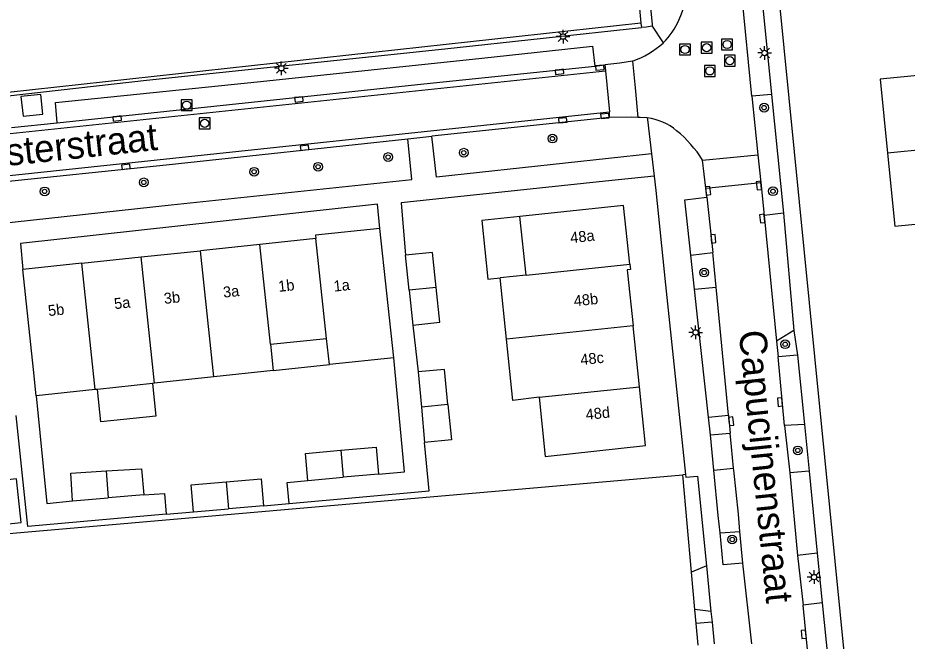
# Model space of a CAD drawing. Extents: x 140000 to 143000, y 403500 to 406000.
# Drawn here: x 140498.4 to 140579.8, y 403927.8 to 403984.8 of the extents above; entities that cross this region are included whole.
import ezdxf

# ---------------------------------------------------------------- set-up
doc = ezdxf.new("R2010")
doc.units = 0
for name, color, linetype in [('gg-afsc-erfafscheiding', 7, 'Continuous'), ('gg-afsc-hekwerk', 7, 'Continuous'), ('gg-anno-huisnummerreeks BGT', 7, 'Continuous'), ('gg-anno-openbare ruimte label', 7, 'Continuous'), ('gg-bbg-bijgebouw', 7, 'Continuous'), ('gg-bbg-hoofdgebouw', 7, 'Continuous'), ('gg-bbg-luifel en loopbrug', 7, 'Continuous'), ('gg-bbg-tussenscheiding', 7, 'Continuous'), ('gg-knt-verharding', 7, 'Continuous'), ('gg-knt-verharding nz', 7, 'Continuous'), ('gg-kwrk-afval apart plaats', 7, 'Continuous'), ('gt-grn-groengrens', 7, 'Continuous'), ('gt-grn-weggrens', 7, 'Continuous'), ('gt-symb-boom', 7, 'Continuous'), ('gt-symb-kolk', 7, 'Continuous'), ('gt-symb-lichtmast', 7, 'Continuous'), ('gt-symb-rioolschacht', 7, 'Continuous')]:
    doc.layers.add(name, color=color, linetype=linetype)

# ---------------------------------------------------------------- blocks, each defined once
blk = doc.blocks.new('gt0-BOOM')
at = {"layer": 'gt-symb-boom'}
for radius in [0.4, 0.2]:
    blk.add_circle((0, 0), radius, dxfattribs=at)
blk = doc.blocks.new('gt0-RS')
at = {"layer": 'gt-symb-rioolschacht'}
blk.add_lwpolyline([(-0.5, -0.5), (0.5, -0.5), (0.5, 0.5), (-0.5, 0.5)], close=True, dxfattribs=at)
blk.add_circle((0, 0), 0.375, dxfattribs=at)
blk = doc.blocks.new('gt0-KOLK')
at = {"layer": 'gt-symb-kolk'}
blk.add_lwpolyline([(0, 0), (0.375, 0), (0.375, 0.4), (-0.375, 0.4), (-0.375, 0), (0, 0)], dxfattribs=at)
blk = doc.blocks.new('gt0-LMAST')
at = {"layer": 'gt-symb-lichtmast'}
for p, q in [((-0.182, 0.173), (-0.447, 0.438)), ((-0.005, 0.246), (-0.005, 0.621)), ((0.172, 0.173), (0.437, 0.438)), ((-0.255, -0.004), (-0.63, -0.004)), ((-0.182, -0.181), (-0.447, -0.446)), ((-0.005, -0.254), (-0.005, -0.629)), ((0.437, -0.446), (0.172, -0.181)), ((0.245, -0.004), (0.62, -0.004))]:
    blk.add_line(p, q, dxfattribs=at)
blk.add_circle((-0.005, -0.004), 0.25, dxfattribs=at)

msp = doc.modelspace()

# ---------------------------------------------------------------- linework, layer by layer
at = {"layer": 'gg-afsc-erfafscheiding'}
for p, q in [((140477.872, 403935.89), (140559.274, 403942.987)), ((140559.502, 403943.006), (140559.274, 403942.987)), ((140560.063, 403934.086), (140559.274, 403942.987)), ((140520.86, 403940.149), (140523.207, 403940.362)), ((140511.943, 403939.396), (140514.462, 403939.588)), ((140560.481, 403929.367), (140560.368, 403930.645)), ((140560.657, 403927.39), (140560.481, 403929.367))]:
    msp.add_line(p, q, dxfattribs=at)
at = {"layer": 'gg-afsc-hekwerk'}
msp.add_lwpolyline([(140555.427, 403984.336), (140484.069, 403976.529), (140484.106, 403976.189)], dxfattribs=at)
at = {"layer": 'gg-bbg-bijgebouw'}
for p, q in [((140534.208, 403959.896), (140533.866, 403963.1)), ((140534.208, 403959.896), (140534.549, 403956.691)), ((140535.013, 403952.41), (140535.314, 403949.178)), ((140535.314, 403949.178), (140535.614, 403945.946)), ((140524.935, 403942.467), (140528.169, 403942.76)), ((140531.402, 403943.053), (140528.169, 403942.76)), ((140503.364, 403940.596), (140506.632, 403940.877)), ((140509.9, 403941.157), (140506.632, 403940.877)), ((140520.86, 403940.149), (140517.661, 403939.868)), ((140514.462, 403939.588), (140517.661, 403939.868))]:
    msp.add_line(p, q, dxfattribs=at)
for points in [[(140536.673, 403960.153), (140536.347, 403963.353), (140533.866, 403963.1)], [(140534.549, 403956.691), (140536.999, 403956.952), (140536.673, 403960.153)], [(140537.75, 403949.416), (140537.42, 403952.634), (140535.013, 403952.41)], [(140537.75, 403949.416), (140538.079, 403946.199), (140535.614, 403945.946)], [(140524.935, 403942.467), (140524.71, 403944.953), (140527.947, 403945.239)], [(140527.947, 403945.239), (140531.184, 403945.525), (140531.402, 403943.053)], [(140503.364, 403940.596), (140503.21, 403943.155), (140506.453, 403943.349)], [(140506.453, 403943.349), (140509.695, 403943.543), (140509.9, 403941.157)], [(140514.462, 403939.588), (140514.244, 403942.073), (140517.445, 403942.349)], [(140517.445, 403942.349), (140520.646, 403942.626), (140520.86, 403940.149)]]:
    msp.add_lwpolyline(points, dxfattribs=at)
at = {"layer": 'gg-bbg-hoofdgebouw'}
for p, q in [((140544.903, 403961.261), (140544.335, 403966.631)), ((140532.788, 403953.69), (140531.511, 403965.534)), ((140525.666, 403964.619), (140520.534, 403964.078)), ((140509.668, 403962.933), (140515.095, 403963.505)), ((140520.534, 403964.078), (140515.095, 403963.505)), ((140504.24, 403962.362), (140509.668, 403962.933)), ((140504.24, 403962.362), (140498.839, 403961.793)), ((140544.903, 403961.261), (140542.522, 403961.009)), ((140543.106, 403955.405), (140542.522, 403961.009)), ((140555.285, 403951.051), (140554.705, 403956.615)), ((140521.496, 403954.942), (140526.629, 403955.48)), ((140526.911, 403953.097), (140526.629, 403955.48)), ((140521.496, 403954.942), (140521.739, 403952.537)), ((140532.788, 403953.69), (140526.911, 403953.097)), ((140521.739, 403952.537), (140516.312, 403951.954)), ((140510.686, 403951.351), (140505.658, 403950.81)), ((140510.885, 403951.372), (140510.686, 403951.351)), ((140516.312, 403951.954), (140510.885, 403951.372)), ((140505.459, 403950.789), (140500.032, 403950.206)), ((140505.658, 403950.81), (140505.459, 403950.789))]:
    msp.add_line(p, q, dxfattribs=at)
for points in [[(140589.429, 403973.63), (140589.2, 403975.972), (140588.769, 403980.314), (140583.89, 403979.841), (140577.33, 403979.202), (140578.011, 403972.421)], [(140578.011, 403972.421), (140578.68, 403965.752), (140583.65, 403966.252), (140585.427, 403966.431), (140590.354, 403966.909), (140589.976, 403970.299), (140593.202, 403970.617), (140592.922, 403973.971), (140589.429, 403973.63)], [(140554.404, 403962.289), (140553.825, 403967.639), (140544.335, 403966.631)], [(140531.511, 403965.534), (140531.506, 403965.526), (140525.635, 403964.916), (140525.666, 403964.619)], [(140554.404, 403962.289), (140554.458, 403961.798), (140554.168, 403961.768), (140554.202, 403961.442), (140554.705, 403956.615)], [(140500.032, 403950.206), (140499.796, 403952.62), (140498.839, 403961.793)], [(140546.117, 403950.095), (140543.689, 403949.802), (140543.106, 403955.405)], [(140546.117, 403950.095), (140546.658, 403944.678), (140555.847, 403945.663), (140555.285, 403951.051)]]:
    msp.add_lwpolyline(points, dxfattribs=at)
at = {"layer": 'gg-bbg-luifel en loopbrug'}
msp.add_line((140521.739, 403952.537), (140526.911, 403953.097), dxfattribs=at)
for points in [[(140544.335, 403966.631), (140540.852, 403966.262), (140541.415, 403960.898), (140542.522, 403961.009)], [(140510.686, 403951.351), (140511.007, 403948.368), (140505.978, 403947.828), (140505.658, 403950.81)], [(140495.274, 403942.301), (140495.682, 403938.322), (140498.666, 403938.628), (140498.258, 403942.607), (140495.274, 403942.301)]]:
    msp.add_lwpolyline(points, dxfattribs=at)
at = {"layer": 'gg-bbg-tussenscheiding'}
for p, q in [((140589.429, 403973.63), (140578.011, 403972.421)), ((140526.629, 403955.48), (140525.666, 403964.619)), ((140516.312, 403951.954), (140515.095, 403963.505)), ((140521.496, 403954.942), (140520.534, 403964.078)), ((140510.885, 403951.372), (140509.668, 403962.933)), ((140505.459, 403950.789), (140504.24, 403962.362)), ((140544.903, 403961.261), (140554.404, 403962.289)), ((140536.673, 403960.153), (140534.208, 403959.896)), ((140554.705, 403956.615), (140543.106, 403955.405)), ((140546.117, 403950.095), (140555.285, 403951.051)), ((140537.75, 403949.416), (140535.314, 403949.178)), ((140527.947, 403945.239), (140528.169, 403942.76)), ((140506.453, 403943.349), (140506.632, 403940.877)), ((140517.445, 403942.349), (140517.661, 403939.868))]:
    msp.add_line(p, q, dxfattribs=at)
at = {"layer": 'gg-knt-verharding'}
for p, q in [((140604.366, 403622.979), (140559.755, 404069.979)), ((140566.385, 403987.711), (140567.367, 403977.797)), ((140556.458, 403984.071), (140557.473, 403982.548)), ((140551.189, 403980.409), (140552.107, 403980.509)), ((140552.107, 403980.509), (140552.175, 403979.979)), ((140552.175, 403979.979), (140552.551, 403976.217)), ((140567.367, 403977.797), (140565.589, 403977.649)), ((140565.589, 403977.649), (140566.133, 403972.297)), ((140567.367, 403977.797), (140568.47, 403966.951)), ((140552.557, 403975.687), (140552.551, 403976.217)), ((140497.791, 403974.795), (140501.969, 403975.223)), ((140552.557, 403975.687), (140536.289, 403973.981)), ((140534.063, 403973.743), (140536.289, 403973.981)), ((140556.404, 403972.362), (140556.626, 403970.345)), ((140561.072, 403971.806), (140566.133, 403972.297)), ((140561.352, 403969.231), (140561.072, 403971.806)), ((140566.133, 403972.297), (140566.392, 403969.753)), ((140561.352, 403969.231), (140566.392, 403969.753)), ((140561.442, 403968.396), (140561.352, 403969.231)), ((140566.392, 403969.753), (140566.7, 403966.719)), ((140568.47, 403966.951), (140566.7, 403966.719)), ((140568.47, 403966.951), (140569.432, 403956.215)), ((140559.999, 403963.109), (140561.992, 403963.33)), ((140560.33, 403959.981), (140559.999, 403963.109)), ((140562.298, 403960.171), (140561.992, 403963.33)), ((140560.33, 403959.981), (140562.298, 403960.171)), ((140534.549, 403956.691), (140535.013, 403952.41)), ((140569.432, 403956.215), (140567.837, 403955.236)), ((140569.432, 403956.215), (140569.755, 403953.93)), ((140567.837, 403955.236), (140568, 403953.786)), ((140569.755, 403953.93), (140568, 403953.786)), ((140569.755, 403953.93), (140570.404, 403947.6)), ((140561.61, 403948.258), (140563.43, 403948.446)), ((140561.782, 403946.641), (140561.61, 403948.258)), ((140563.43, 403948.446), (140563.588, 403946.815)), ((140570.404, 403947.6), (140568.561, 403947.493)), ((140568.561, 403947.493), (140569.048, 403943.159)), ((140570.404, 403947.6), (140570.82, 403943.334)), ((140561.782, 403946.641), (140563.588, 403946.815)), ((140562.099, 403943.418), (140561.782, 403946.641)), ((140562.099, 403943.418), (140563.913, 403943.592)), ((140570.82, 403943.334), (140569.048, 403943.159)), ((140570.82, 403943.334), (140571.547, 403935.81)), ((140562.663, 403937.675), (140564.488, 403937.808)), ((140564.744, 403934.909), (140564.488, 403937.808)), ((140571.547, 403935.81), (140569.766, 403935.612)), ((140569.766, 403935.612), (140570.278, 403931.048)), ((140571.547, 403935.81), (140572.017, 403931.277)), ((140561.417, 403934.665), (140560.063, 403934.086)), ((140561.417, 403934.665), (140561.836, 403930.465)), ((140565.565, 403927.508), (140564.744, 403934.909)), ((140560.368, 403930.645), (140560.063, 403934.086)), ((140572.017, 403931.277), (140570.278, 403931.048)), ((140572.017, 403931.277), (140572.655, 403924.957)), ((140561.836, 403930.465), (140560.368, 403930.645)), ((140561.836, 403930.465), (140561.933, 403929.496)), ((140561.933, 403929.496), (140560.481, 403929.367)), ((140561.933, 403929.496), (140562.13, 403927.521))]:
    msp.add_line(p, q, dxfattribs=at)
for points in [[(140546.163, 404087.643), (140556.445, 403984.205), (140556.458, 403984.071)], [(140484.494, 403976.231), (140510.138, 403979.108), (140537.462, 403981.986), (140555.467, 403983.938)], [(140556.458, 403984.071), (140555.896, 403983.984), (140555.467, 403983.938)], [(140501.969, 403975.223), (140501.817, 403977.063), (140520.589, 403978.991), (140540.863, 403981.13), (140551.001, 403982.234), (140551.189, 403980.409)], [(140554.638, 403980.847), (140553.476, 403980.668), (140552.107, 403980.509)], [(140554.638, 403980.847), (140554.895, 403978.412), (140555.126, 403975.712)], [(140501.969, 403975.223), (140535.542, 403978.791), (140551.189, 403980.409)], [(140555.126, 403975.712), (140554.592, 403975.732), (140552.557, 403975.687)], [(140556.007, 403975.668), (140555.364, 403975.703), (140555.126, 403975.712)], [(140556.007, 403975.668), (140556.026, 403975.508), (140556.404, 403972.362)], [(140496.008, 403969.714), (140496.405, 403965.97), (140512.411, 403967.715), (140534.443, 403970.018), (140534.063, 403973.743)], [(140496.008, 403969.714), (140511.958, 403971.373), (140534.063, 403973.743)], [(140556.404, 403972.362), (140536.696, 403970.244), (140536.289, 403973.981)], [(140556.626, 403970.345), (140552.189, 403969.88), (140533.453, 403967.901), (140533.866, 403963.1)], [(140556.626, 403970.345), (140556.774, 403969.02), (140557.667, 403960.371), (140559.502, 403943.006)], [(140559.999, 403963.109), (140559.451, 403968.159), (140561.442, 403968.396)], [(140531.511, 403965.534), (140531.296, 403967.764), (140498.601, 403964.167), (140498.839, 403961.793)], [(140561.61, 403948.258), (140560.641, 403957.136), (140560.33, 403959.981)], [(140563.43, 403948.446), (140562.573, 403957.322), (140562.298, 403960.171)], [(140531.402, 403943.053), (140533.759, 403943.267), (140532.788, 403953.69)], [(140500.032, 403950.206), (140501.03, 403940.359), (140503.364, 403940.596)], [(140511.943, 403939.396), (140499.268, 403938.257), (140498.226, 403948.429)], [(140523.207, 403940.362), (140536.045, 403941.529), (140535.614, 403945.946)], [(140562.663, 403937.675), (140562.507, 403939.259), (140562.099, 403943.418)], [(140564.488, 403937.808), (140564.348, 403939.393), (140563.932, 403943.407), (140563.913, 403943.592)], [(140523.207, 403940.362), (140523.032, 403942.294), (140524.935, 403942.467)], [(140559.502, 403943.006), (140559.527, 403942.774), (140560.598, 403942.863), (140561.417, 403934.665)], [(140509.9, 403941.157), (140511.782, 403941.28), (140511.943, 403939.396)], [(140564.744, 403934.909), (140562.951, 403934.736), (140562.663, 403937.675)]]:
    msp.add_lwpolyline(points, dxfattribs=at)
for centre, radius, start, end in [((140553.471, 403987.249), 6.036, 334.25297, 7.6851), ((140552.839, 403987.278), 6.622, 314.41011, 336.39759), ((140551.833, 403988.736), 8.373, 289.57671, 312.35081), ((140555.345, 403970.506), 5.205, 49.98882, 82.68973), ((140551.54, 403965.754), 11.291, 32.40934, 50.70132)]:
    msp.add_arc(centre, radius, start, end, dxfattribs=at)
at = {"layer": 'gg-knt-verharding nz'}
for p, q in [((140565.589, 403977.649), (140564.596, 403987.532)), ((140561.442, 403968.396), (140561.992, 403963.33)), ((140566.7, 403966.719), (140567.837, 403955.236)), ((140568.561, 403947.493), (140568, 403953.786)), ((140569.048, 403943.159), (140569.766, 403935.612))]:
    msp.add_line(p, q, dxfattribs=at)
for points in [[(140563.913, 403943.592), (140563.71, 403945.542), (140563.588, 403946.815)], [(140570.877, 403924.813), (140570.874, 403924.838), (140570.278, 403931.048)]]:
    msp.add_lwpolyline(points, dxfattribs=at)
at = {"layer": 'gg-kwrk-afval apart plaats'}
msp.add_lwpolyline([(140498.655, 403977.622), (140498.847, 403975.815), (140500.651, 403976.003), (140500.466, 403977.82), (140498.655, 403977.622)], dxfattribs=at)
at = {"layer": 'gt-grn-groengrens'}
for p, q in [((140545.173, 404087.488), (140555.427, 403984.336)), ((140555.427, 403984.336), (140555.467, 403983.938))]:
    msp.add_line(p, q, dxfattribs=at)
at = {"layer": 'gt-grn-weggrens'}
msp.add_line((140480.72, 403972.447), (140552.175, 403979.979), dxfattribs=at)
msp.add_lwpolyline([(140481.112, 403968.667), (140490.084, 403969.605), (140552.551, 403976.217)], dxfattribs=at)

# ---------------------------------------------------------------- block references
at = {"layer": 'gt-symb-boom'}
for p in [(140566.7, 403976.601), (140547.318, 403973.767), (140532.266, 403972.082), (140539.197, 403972.479), (140520.004, 403970.737), (140525.862, 403971.195), (140509.902, 403969.763), (140500.821, 403968.937), (140567.514, 403968.946), (140561.212, 403961.503), (140568.628, 403954.943), (140569.787, 403945.224), (140563.781, 403937.067)]:
    msp.add_blockref('gt0-BOOM', p, dxfattribs=at)
at = {"layer": 'gt-symb-kolk'}
for p, rotation in [((140547.946, 403980.074), -174.0982878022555), ((140551.637, 403980.458), -174.01718369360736), ((140524.084, 403977.553), -174.52065066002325), ((140507.441, 403975.805), -173.93608067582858), ((140552.143, 403975.644), 5.990842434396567), ((140548.287, 403975.239), 5.990842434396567), ((140524.638, 403972.732), 6.120088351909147), ((140508.288, 403970.991), 5.941846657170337), ((140561.38, 403968.975), -83.83090908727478), ((140566.418, 403969.492), 95.80373342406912), ((140566.724, 403966.472), 95.65839657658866), ((140561.857, 403964.574), -83.80684128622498), ((140568.367, 403949.665), 95.09068261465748), ((140563.485, 403947.878), -84.46365037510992), ((140570.532, 403928.404), 95.47934933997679)]:
    msp.add_blockref('gt0-KOLK', p, dxfattribs=dict(at, rotation=rotation))
at = {"layer": 'gt-symb-lichtmast'}
for p in [(140548.292, 403983.112), (140566.744, 403981.612), (140522.497, 403980.22), (140560.43, 403956.025), (140571.283, 403933.628)]:
    msp.add_blockref('gt0-LMAST', p, dxfattribs=at)
at = {"layer": 'gt-symb-rioolschacht'}
for p in [(140559.457, 403981.927), (140561.436, 403982.093), (140563.313, 403982.385), (140563.564, 403980.898), (140561.729, 403979.968), (140513.821, 403976.827), (140515.476, 403975.166)]:
    msp.add_blockref('gt0-RS', p, dxfattribs=at)

# ---------------------------------------------------------------- texts
at = {"layer": 'gg-anno-huisnummerreeks BGT'}
for s, rotation, p in [('48a', 6.2, (140549.002, 403964.194)), ('3a', 6, (140517.209, 403959.204)), ('1b', 6, (140522.259, 403959.736)), ('1a', 6.2, (140527.33, 403959.754)), ('3b', 6, (140511.789, 403958.632)), ('48b', 5.9, (140549.324, 403958.408)), ('5b', 6, (140501.183, 403957.516)), ('5a', 6, (140507.232, 403958.152)), ('48c', 6, (140549.925, 403953.029)), ('48d', 6, (140550.409, 403948.007))]:
    msp.add_text(s, height=1, rotation=rotation, dxfattribs=at).set_placement(p)
at = {"layer": 'gg-anno-openbare ruimte label'}
for s, rotation, p in [('Kloosterstraat', 6.1, (140490.74, 403970.55)), ('Capucijnenstraat', 275.8, (140564.375, 403956.118))]:
    msp.add_text(s, height=2.5, rotation=rotation, dxfattribs=at).set_placement(p)

doc.saveas('drawing.dxf')
